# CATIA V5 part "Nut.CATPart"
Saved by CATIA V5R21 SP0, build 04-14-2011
Part number: nut
Bounding box of the stored display mesh (mm): x -13.856 to 13.856, y 0 to 9, z -12 to 12
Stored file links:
  D:\CATIA V5R21 E-RESOURCES\CATIA-V5R21\catia-v5r21-Prts\c12_catia_v5r21_prt\c12_catia_v5r21figr_12-54 to 56\Nut.CATPart
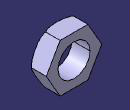
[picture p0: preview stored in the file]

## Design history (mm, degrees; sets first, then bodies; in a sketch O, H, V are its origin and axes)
Body1 (main body)
  Sketch1 on zx-plane, origin (0, 0, 0), H (-1, 0, 0), V (0, 0, 1)
    circle A1 centre (0, 0) radius 8
    construction circle A2 centre (0, 0) radius 12
    point P1 (-6.9282, -12)
    point P2 (6.9282, -12)
    point P3 (13.8564, 0)
    point P4 (6.9282, 12)
    point P5 (-6.9282, 12)
    point P6 (-13.8564, 0)
    point P7 (0, -12)
    line L1 (-6.9282, -12) -> (6.9282, -12)
    line L2 (6.9282, -12) -> (13.8564, 0)
    line L3 (13.8564, 0) -> (6.9282, 12)
    line L4 (6.9282, 12) -> (-6.9282, 12)
    line L5 (-6.9282, 12) -> (-13.8564, 0)
    line L6 (-13.8564, 0) -> (-6.9282, -12)
    construction line L7 (0, 0) -> (0, -12)
    construction circle A3 centre (0, 0) radius 13.8564
    construction arc A4 centre (-6.9282, 12) radius 13.8564 from (6.9282, 12) to (-13.8564, 0) cw
    construction arc A5 centre (6.9282, -12) radius 13.8564 from (13.8564, 0) to (-6.9282, -12) ccw
    radius A1 = 8
    radius A2 = 12
    coincidence: P7 A2, A3 P1, A3 P2, A3 P3, A3 P4, A3 P5, A3 P6, A4 O, A5 O
    vertical: L7 V
    midpoint: P7 L1
    parallelism: L1 L4
  Pad1: profile Sketch1, direction (0, 1, 0), length 9
  Sketch2 on xy-plane, origin (0, 0, 0), H (1, 0, 0), V (0, 1, 0)
    projected line E1 (10.7061, 0) -> (13.8564, 0) from edge of Pad1
    point P1 (13.8564, 0)
    projected line E2 (13.8564, 0) -> (13.8564, 1.8188) from edge of Pad1
    point P2 (13.8564, 0)
    arc A1 centre (10.7061, 3.6376) radius 3.6376 from (10.7061, 0) to (13.8564, 1.8188) ccw
    coincidence: P1 P2
    tangency: A1 E1
  Groove1: profile Sketch2, axis axis of face of Pad1, angle 360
